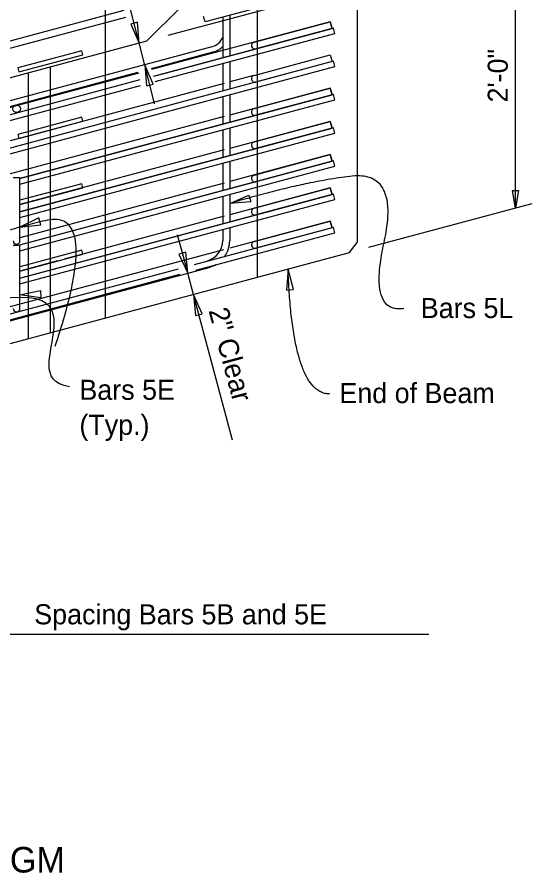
# Model space of a CAD drawing. Extents: x 0.8 to 30.4, y 0.3 to 18.9.
# Drawn here: x 26.37 to 30.25, y 1.87 to 8.31 of the extents above; entities that cross this region are included whole.
import ezdxf

# ---------------------------------------------------------------- set-up
doc = ezdxf.new("R2010")
doc.units = 0
for name, color, linetype in [('BeamConc', 7, 'Continuous'), ('BeamConc_h', 7, 'Continuous'), ('Dimension', 7, 'Continuous'), ('Miscellaneous', 7, 'Continuous'), ('Rebar', 7, 'Continuous'), ('Rebar_h', 7, 'Continuous'), ('TextStructures', 7, 'Continuous')]:
    doc.layers.add(name, color=color, linetype=linetype)

msp = doc.modelspace()

# ---------------------------------------------------------------- linework, layer by layer
at = {"layer": 'BeamConc'}
for p, q in [((28.9316, 9.5235), (28.9316, 6.6147)), ((27.5982, 8.3779), (27.3482, 8.1279)), ((27.3482, 8.1279), (26.2769, 7.8408)), ((28.8712, 6.536), (28.9316, 6.6147)), ((28.8712, 6.536), (21.4512, 4.5478))]:
    msp.add_line(p, q, dxfattribs=at)
at = {"layer": 'BeamConc_h'}
for p, q in [((28.1816, 6.3512), (28.1816, 9.3226)), ((27.0357, 9.0157), (27.0357, 6.0442))]:
    msp.add_line(p, q, dxfattribs=at)
at = {"layer": 'Dimension'}
for p, q in [((27.2929, 8.1131), (27.0263, 9.1662)), ((30.224, 8.8985), (27.5072, 8.1705)), ((30.1238, 6.8716), (30.1238, 8.8716)), ((27.3396, 8.1256), (27.3396, 8.1256)), ((27.3325, 7.9569), (27.294, 8.1088)), ((27.4081, 7.658), (27.3338, 7.9515)), ((27.3827, 7.9646), (27.3827, 7.9646)), ((30.2473, 6.9047), (29.0185, 6.5754)), ((27.5789, 6.6753), (27.6571, 6.3832)), ((27.7003, 6.2222), (27.6571, 6.3832)), ((27.7302, 6.4028), (27.7302, 6.4028)), ((27.6272, 6.2026), (27.6272, 6.2026)), ((27.9938, 5.1267), (27.7003, 6.2222)), ((29.4729, 3.6652), (23.0357, 3.6652))]:
    msp.add_line(p, q, dxfattribs=at)
for points in [[(27.2929, 8.1131), (27.2802, 8.271), (27.2289, 8.258)], [(27.3338, 7.9515), (27.3465, 7.7936), (27.3978, 7.8065)], [(27.9732, 6.9071), (28.1182, 6.971), (28.1312, 6.9197)], [(30.1238, 6.8714), (30.1017, 7.0052), (30.1459, 7.0052)], [(26.3951, 6.7289), (26.5524, 6.7481), (26.5373, 6.7988)], [(27.6571, 6.3832), (27.6423, 6.5409), (27.5912, 6.5272)], [(28.4125, 6.413), (28.3995, 6.2551), (28.4522, 6.2596)], [(26.3951, 6.2206), (26.5505, 6.2516), (26.552, 6.1987)], [(27.7003, 6.2222), (27.7151, 6.0645), (27.7663, 6.0782)]]:
    msp.add_lwpolyline(points, close=True, dxfattribs=at)
for points, degree in [([(29.2838, 6.1167), (29.0154, 6.0771), (29.2555, 7.1567), (28.5095, 7.0669), (27.9732, 6.9072)], 2), ([(26.6609, 5.834), (27.0095, 6.8858), (26.159, 6.67), (25.7284, 6.5418)], 2), ([(28.7267, 5.4738), (28.4462, 5.4738), (28.4124, 6.413)], 2), ([(26.7677, 5.5283), (26.5259, 5.5675), (26.7502, 5.9972), (26.5827, 6.3303), (25.7284, 6.056)], 3)]:
    msp.add_open_spline(points, degree=degree, dxfattribs=at)
at = {"layer": 'Miscellaneous'}
for p, q in [((26.6232, 7.9336), (26.6232, 5.9336)), ((26.4565, 7.889), (26.4565, 5.889))]:
    msp.add_line(p, q, dxfattribs=at)
at = {"layer": 'Rebar'}
for p, q in [((28.7541, 8.5329), (27.7881, 8.2741)), ((27.7881, 8.2741), (27.7773, 8.3144)), ((27.9212, 8.3097), (27.9212, 8.0044)), ((27.9732, 8.3237), (27.9732, 8.0184)), ((28.1565, 8.1214), (28.7302, 8.2752)), ((28.7302, 8.2752), (28.7437, 8.2248)), ((28.7541, 8.2276), (27.3964, 7.8638)), ((27.4114, 7.8247), (28.7649, 8.1874)), ((28.7437, 8.2248), (28.17, 8.0711)), ((28.7649, 8.1874), (28.7541, 8.2276)), ((27.8389, 8.0868), (23.7025, 6.9785)), ((27.384, 7.9232), (27.8497, 8.048)), ((28.1565, 7.8714), (28.7302, 8.0252)), ((28.7302, 8.0252), (28.7437, 7.9748)), ((28.7541, 7.9776), (20.6399, 5.8034)), ((20.6507, 5.7632), (28.7649, 7.9374)), ((27.9212, 7.9613), (27.9212, 7.7544)), ((27.9732, 7.9752), (27.9732, 7.7684)), ((28.7437, 7.9748), (28.17, 7.8211)), ((28.7649, 7.9374), (28.7541, 7.9776)), ((23.695, 6.9348), (27.2809, 7.8956)), ((27.2958, 7.8369), (20.6399, 6.0534)), ((20.6507, 6.0132), (27.3031, 7.7957)), ((28.7541, 7.7276), (26.3951, 7.0955)), ((28.1565, 7.6214), (28.7302, 7.7752)), ((28.7302, 7.7752), (28.7437, 7.7248)), ((28.7649, 7.6874), (28.7541, 7.7276)), ((26.3951, 7.0524), (28.7649, 7.6874)), ((27.9212, 7.7113), (27.9212, 7.5044)), ((27.9732, 7.7252), (27.9732, 7.5184)), ((28.7437, 7.7248), (28.17, 7.5711)), ((28.7541, 7.4776), (26.3951, 6.8455)), ((27.9732, 7.4752), (27.9732, 7.2684)), ((28.1565, 7.3714), (28.7302, 7.5252)), ((28.7437, 7.4748), (28.17, 7.3211)), ((28.7302, 7.5252), (28.7437, 7.4748)), ((28.7649, 7.4374), (28.7541, 7.4776)), ((26.3951, 6.8024), (28.7649, 7.4374)), ((27.9212, 7.4613), (27.9212, 7.2544)), ((28.7541, 7.2276), (26.3806, 6.5916)), ((27.9732, 7.2252), (27.9732, 7.0184)), ((28.1565, 7.1214), (28.7302, 7.2752)), ((28.7437, 7.2248), (28.17, 7.0711)), ((28.7302, 7.2752), (28.7437, 7.2248)), ((28.7649, 7.1874), (28.7541, 7.2276)), ((26.3951, 6.5524), (28.7649, 7.1874)), ((27.9212, 7.2113), (27.9212, 7.0044)), ((26.3951, 7.1016), (26.343, 7.1016)), ((26.3951, 6.6277), (26.3951, 7.1016)), ((28.1565, 6.8714), (28.7302, 7.0252)), ((28.7302, 7.0252), (28.7437, 6.9748)), ((28.7541, 6.9776), (26.3978, 6.3462)), ((27.9212, 6.9613), (27.9212, 6.7544)), ((27.9732, 6.9752), (27.9732, 6.7684)), ((28.7437, 6.9748), (28.17, 6.8211)), ((28.7649, 6.9374), (28.7541, 6.9776)), ((26.3951, 6.3024), (28.7649, 6.9374)), ((28.1565, 6.6214), (28.7302, 6.7752)), ((28.7302, 6.7752), (28.7437, 6.7248)), ((28.7541, 6.7276), (27.7063, 6.4468)), ((27.9211, 6.7113), (27.9211, 6.6278)), ((27.9732, 6.7252), (27.9732, 6.6278)), ((28.7437, 6.7248), (28.17, 6.5711)), ((28.7649, 6.6874), (28.7541, 6.7276)), ((27.7173, 6.4067), (28.7649, 6.6874)), ((26.3951, 6.5916), (26.343, 6.5916)), ((26.3951, 6.1177), (26.3951, 6.5916)), ((27.5855, 6.4145), (20.6399, 4.5534)), ((21.6938, 4.7854), (27.8189, 6.4266)), ((20.6507, 4.5132), (27.598, 6.3747))]:
    msp.add_line(p, q, dxfattribs=at)
for points in [[(26.3861, 7.897), (26.8691, 8.0264), (26.861, 8.0566), (26.378, 7.9272)], [(26.3861, 7.397), (26.8691, 7.5264), (26.861, 7.5566), (26.378, 7.4272)]]:
    msp.add_lwpolyline(points, close=True, dxfattribs=at)
for points in [[(26.3951, 6.8456), (28.7437, 7.4749), (28.7302, 7.5251), (27.9732, 7.3223)], [(26.3951, 6.8994), (26.8691, 7.0264), (26.861, 7.0566), (26.3951, 6.9318)], [(26.3951, 6.3994), (26.8691, 6.5264), (26.861, 6.5566), (26.3951, 6.4318)]]:
    msp.add_lwpolyline(points, dxfattribs=at)
msp.add_circle((26.3691, 7.6201), 0.0287, dxfattribs=at)
for centre, radius, start, end in [((27.8066, 8.2075), 0.125, 285, 336.44353), ((28.1632, 8.0963), 0.026, 105, 285), ((27.8065, 8.209), 0.1667, 285, 313.43746), ((28.1632, 7.8463), 0.026, 105, 285), ((28.1632, 7.5963), 0.026, 105, 285), ((28.1632, 7.3463), 0.026, 105, 285), ((28.1632, 7.0963), 0.026, 105, 285), ((28.1632, 6.8463), 0.026, 105, 285), ((26.3691, 6.6277), 0.026, 179.99982, 359.99949), ((27.7649, 6.6278), 0.1562, 285, 360), ((27.7649, 6.6278), 0.2083, 324.99028, 360), ((28.1632, 6.5963), 0.026, 105, 285), ((27.7649, 6.6278), 0.2083, 285, 299.93885), ((26.3691, 6.1177), 0.026, 179.99982, 359.99949)]:
    msp.add_arc(centre, radius, start, end, dxfattribs=at)
at = {"layer": 'Rebar_h'}
for p, q in [((21.2385, 6.7139), (27.1911, 8.3089)), ((27.1777, 8.3591), (21.6267, 6.8717)), ((28.7302, 8.2751), (27.3843, 7.9145)), ((28.7437, 8.2249), (28.7302, 8.2751)), ((27.4223, 7.8708), (28.7437, 8.2249)), ((27.2888, 7.8889), (20.6513, 6.1104)), ((28.7302, 6.7751), (27.9732, 6.5723)), ((28.7437, 6.7249), (28.7302, 6.7751)), ((27.9267, 6.5598), (25.7284, 5.9708))]:
    msp.add_line(p, q, dxfattribs=at)
for points in [[(28.1553, 7.8711), (27.9732, 7.8223)], [(27.9316, 7.8111), (21.4733, 6.0806)], [(26.3951, 7.0956), (28.7437, 7.7249), (28.7302, 7.7751), (27.9732, 7.5723)], [(27.9316, 7.5611), (21.4733, 5.8306)], [(27.9316, 7.3111), (26.3951, 6.8994)], [(26.3951, 6.5956), (28.7437, 7.2249), (28.7302, 7.2751), (27.9732, 7.0723)], [(27.9316, 7.0611), (26.3951, 6.6494)], [(26.3951, 6.3456), (28.7437, 6.9749), (28.7302, 7.0251), (27.9732, 6.8223)], [(27.9316, 6.8111), (26.7284, 6.4888)], [(26.6764, 6.4748), (26.3951, 6.3994)]]:
    msp.add_lwpolyline(points, dxfattribs=at)

# ---------------------------------------------------------------- texts
at = {"layer": 'Dimension'}
for s, height, p in [('Bars 5E ', 0.1512, (26.8421, 5.4302)), ('(Typ.)', 0.1512, (26.8421, 5.1662)), ('TOP VIEW OF SKEWED END DIAPHRAGM', 0.192, (21.626, 1.8732))]:
    msp.add_text(s, height=height, dxfattribs=at).set_placement(p)
at = {"layer": 'TextStructures'}
for s, rotation, p in [('2\'-0"', 90, (30.066, 7.6678)), ('2" Clear', 285, (27.8129, 6.1027))]:
    msp.add_text(s, height=0.1512, rotation=rotation, dxfattribs=at).set_placement(p)
for s, p in [('Bars 5L', (29.4112, 6.0453)), ('End of Beam', (28.7987, 5.4055)), ('Spacing Bars 5B and 5E', (26.5023, 3.7406))]:
    msp.add_text(s, height=0.1512, dxfattribs=at).set_placement(p)

doc.saveas('drawing.dxf')
